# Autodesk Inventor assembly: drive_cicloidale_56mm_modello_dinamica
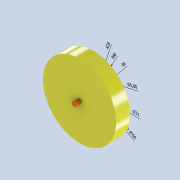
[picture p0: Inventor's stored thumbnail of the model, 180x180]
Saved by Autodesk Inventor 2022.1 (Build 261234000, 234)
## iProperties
Created: 2022-04
Part Number: drive_cicloidale_56mm_modello_dinamica
Document SubType Name: Assembly
Designer: i911900
Author: i911900
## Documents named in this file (6)
- C:\Users\i911900\Desktop\cyclo_medium\56mm v2\drive_cicloidale_56mm_modello_dinamica.iam
- C:\Users\i911900\Desktop\cyclo_medium\56mm v2\disco1.ipt
- C:\Users\i911900\Desktop\cyclo_medium\56mm v2\ruota.ipt
- C:\Users\i911900\Desktop\cyclo_medium\56mm v2\piolo.ipt
- C:\Users\i911900\Desktop\cyclo_medium\56mm v2\albero.ipt
- C:\Users\i911900\Desktop\cyclo_medium\56mm v2\disco2.ipt
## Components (15 placed, 5 different names)
1. disco1:1 — Rigido:4, Rigido:3, Rigido:5, Rigido:6, Rigido:7, Rigido:8, Rigido:9, Rigido:10, Rigido:11, Rigido:12, Rigido:13, Coincidente:1
2. piolo:1 — Rigido:4, Transitorio:2
3. piolo:2 — Rigido:3, Transitorio:1
4. piolo:3 — Rigido:5
5. piolo:4 — Rigido:9
6. piolo:5 — Rigido:10
7. piolo:6 — Rigido:12
8. piolo:7 — Rigido:11
9. piolo:8 — Rigido:7
10. piolo:9 — Rigido:6
11. piolo:10 — Rigido:8
12. piolo:11 — Rigido:13
13. disco2:1 — Coincidente:4
14. ruota:1 — Coincidente:3, Transitorio:1, Transitorio:2
15. albero:1 — Coincidente:1, Coincidente:3, Coincidente:4
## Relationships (16: WeldJoint 11, Mate 3, Transitional 2)
- Rigido:4 [WeldJoint]: disco1:1 ↔ piolo:1
- Rigido:3 [WeldJoint]: disco1:1 ↔ piolo:2
- Rigido:5 [WeldJoint]: disco1:1 ↔ piolo:3
- Rigido:6 [WeldJoint]: disco1:1 ↔ piolo:9
- Rigido:7 [WeldJoint]: disco1:1 ↔ piolo:8
- Rigido:8 [WeldJoint]: disco1:1 ↔ piolo:10
- Rigido:9 [WeldJoint]: disco1:1 ↔ piolo:4
- Rigido:10 [WeldJoint]: disco1:1 ↔ piolo:5
- Rigido:11 [WeldJoint]: disco1:1 ↔ piolo:7
- Rigido:12 [WeldJoint]: disco1:1 ↔ piolo:6
- Rigido:13 [WeldJoint]: disco1:1 ↔ piolo:11
- Coincidente:1 [Mate]: disco1:1 ↔ albero:1
- Coincidente:3 [Mate]: ruota:1 ↔ albero:1
- Coincidente:4 [Mate]: disco2:1 ↔ albero:1
- Transitorio:1: piolo:2 ↔ ruota:1
- Transitorio:2: piolo:1 ↔ ruota:1
